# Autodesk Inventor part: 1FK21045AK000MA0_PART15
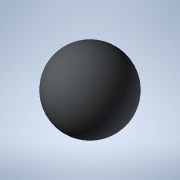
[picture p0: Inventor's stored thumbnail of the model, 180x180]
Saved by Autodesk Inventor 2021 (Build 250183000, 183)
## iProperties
Created: 2025-04
Part Number: 1FK21045AK000MA0_PART15
Material: Generic
Catalog Web Link: www.3dfindit.com
Description: -Servo synchronous motor
Document SubType Name: Modeling
Designer: psAdmin
Mass: 0.137258 g
Surface Area: 1.2868 cm^2
Volume: 0.137258 cm^3
Density: 1 g/cm^3
Appearance: PSOLRGB-212-217-219
Category: PARTsolutions
Title: 1FK21045AK000MA0_PART15
Author: Cadenas PARTsolutions
Comments: Servo synchronous motor
Sending System: PARTsolutions
Preprocessor: ST-DEVELOPER v19.3
PSOL_IDENT_0: {$CADENAS_DATA/23d-libs/siemens_ag/_cat_/3d/2f/1fk21045ak000ma0.prj},216 {VTYP=3D},{NB=1FK21045AK000
PSOL_IDENT_1: MA0_PART15},{LINA=1FK21045AK000MA0_PART15},{NN=1FK21045AK000MA0_PART15},{NOPRJ=TRUE},{DATE=19.08.202
PSOL_IDENT_2: 5 14:00:34},{GEOMDATE=30.07.2025 02:01:24},{VERSION=},{LINEID=10},{WBVAR=},{WBNUMERIC=}  {NB=1FK2104
PSOL_IDENT_3: 5AK000MA0_PART15},{LINA=1FK21045AK000MA0_PART15},{KT=DUMMY},{PREVIEW=../../../_pool_/a9/69/p_d211_xx
PSOL_IDENT_4: _00818j.png},{DESCSHORT=SIMOTICS S-1FK2 HD, SINAMICS S210 3AC 400V-480V, 1.7 Nm, 6000 rpm},{DESCLONG=
PSOL_IDENT_5: SIMOTICS S-1FK2 HD servo motor M0=2.4 Nm; PN = 1.07 kW at nN=6000 rpm (380-480 V); PN = 0.75 kW at n
PSOL_IDENT_6: N=3000 rpm (200-240 V); degree of protection IP64; cylindrical shaft D19x40mm; absolute encoder 22-b
PSOL_IDENT_7: it + 12-bit multiturn (encoder AM22DQC); with OCC interface; plug size M17, rotatable; SIMOTICS S-1F
PSOL_IDENT_8: K2 servomotorfor a wide range of uses in industrial environments. SIMOTICS S‑1FK2 servomotors are co
PSOL_IDENT_9: mpact synchronous motors with a high dynamic performance that set themselves apart as a result of th
PSOL_IDENT_10: eir high power density, degree of protection and overload capability. The motors are available in tw
PSOL_IDENT_11: o variants: as High Dynamic variant (highest dynamic performance as a result of the low intrinsic mo
PSOL_IDENT_12: ment of inertia for applications demanding a high dynamic performance with low moved masses) - and a
PSOL_IDENT_13: s Compact variant (precise and stable closed-loop control for medium up to large moved masses as a r
PSOL_IDENT_14: esult of a medium intrinsic moment of inertia). SIMOTICSS‑1FK2 servomotors fully exploit their stren
PSOL_IDENT_15: gths in a system with the SINAMICSS210 frequency converter and simple connection using the one cable
PSOL_IDENT_16: connection (OCC). Advantages include the short control and positioning times, fast and precise corr
PSOL_IDENT_17: ection of disturbing quantities as well as stable control with a high dynamic performance. The servo
PSOL_IDENT_18: motors can be configured to address a wide range of requirements. For example with and without hold
PSOL_IDENT_19: ing brake, IP64 or IP65 degree of protection, singleturn or multiturn absolute encoders - to name ju
PSOL_IDENT_20: st a few. Further, the servomotors are available in different shaft heights extending from 20 to 100
PSOL_IDENT_21: . A shaft sealing ring is available to achieve an IP65 degree of protection and for subsequent mount
PSOL_IDENT_22: ing at the motor or as spare part. SIMOTICS - the optimum motor for each and every motion control ap
PSOL_IDENT_23: plication.},{INTNO=804766789342},{SUPPLIERALTNO=1FK2104-5AK00-0MA0},{MANUID=1FK21045AK000MA0},{MANUN
PSOL_IDENT_24: AME=Siemens},{MANUTYPEDESC=Synchronous motor 1FK2-HD 2,39 Nm},{AAU732=SIMOTICS},{AAO057=S-1FK2},{AAU
PSOL_IDENT_25: 734=SIMOTICS S-1FK2 HD servo motor M0=2.4 Nm; PN = 1.07 kW at nN=6000 rpm (380-480 V); PN = 0.75 kW
PSOL_IDENT_26: at nN=3000 rpm (200-240 V); degree of protection IP64; cylindrical shaft D19x40mm; absolute encoder
PSOL_IDENT_27: 22-bit + 12-bit multiturn (encoder AM22DQC); with OCC interface; plug size M17, rotatable;},{AAW338=
PSOL_IDENT_28: Synchronous motor 1FK2-HD 2,39 Nm},{AAO742=SIMOTICS},{AAO663=4042948691151},{NOCUPEROU=1},{PRICEQUAN
PSOL_IDENT_29: TITY=1},{QUANTITYMIN=1},{QUANTITYINT=1},{CTN=85015100},{COO=DE},{AAO676=1FK2104-5AK00-0MA0},{AAO677=
PSOL_IDENT_30: Siemens AG},{ORDERUNIT=C62},{CONTENTUNIT=C62}
NB: 1FK21045AK000MA0_PART15
NT: Servo synchronous motor
NBSYN: $MANUID._PART15
LINA: 1FK21045AK000MA0_PART15
CATALOG: SIEMENS
PREVIEW: ../../../_pool_/a9/69/p_d211_xx_00818j.png
DESCSHORT: SIMOTICS S-1FK2 HD, SINAMICS S210 3AC 400V-480V, 1.7 Nm, 6000 rpm
DESCLONG: SIMOTICS S-1FK2 HD servo motor M0=2.4 Nm; PN = 1.07 kW at nN=6000 rpm (380-480 V); PN = 0.75 kW at nN=3000 rpm (200-240 V); degree of protection IP64; cylindric
INTNO: 804766789342
SUPPLIERALTNO: 1FK2104-5AK00-0MA0
MANUID: 1FK21045AK000MA0
MANUNAME: Siemens
MANUTYPEDESC: Synchronous motor 1FK2-HD 2,39 Nm
AAU732: SIMOTICS
AAO057: S-1FK2
AAU734: SIMOTICS S-1FK2 HD servo motor M0=2.4 Nm; PN = 1.07 kW at nN=6000 rpm (380-480 V); PN = 0.75 kW at nN=3000 rpm (200-240 V); degree of protection IP64; cylindric
AAW338: Synchronous motor 1FK2-HD 2,39 Nm
AAO742: SIMOTICS
AAO663: 4042948691151.0
NOCUPEROU: 1
PRICEQUANTITY: 1
QUANTITYMIN: 1
QUANTITYINT: 1
CTN: 85015100
COO: DE
ARTICLENO: 1FK21045AK000MA0_PART15
BOMINFO: 1FK21045AK000MA0_PART15
CREATOR: CADENAS GmbH
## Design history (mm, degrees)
feature "2025_04_17_15_39_51_0728"
body "Solid1"
